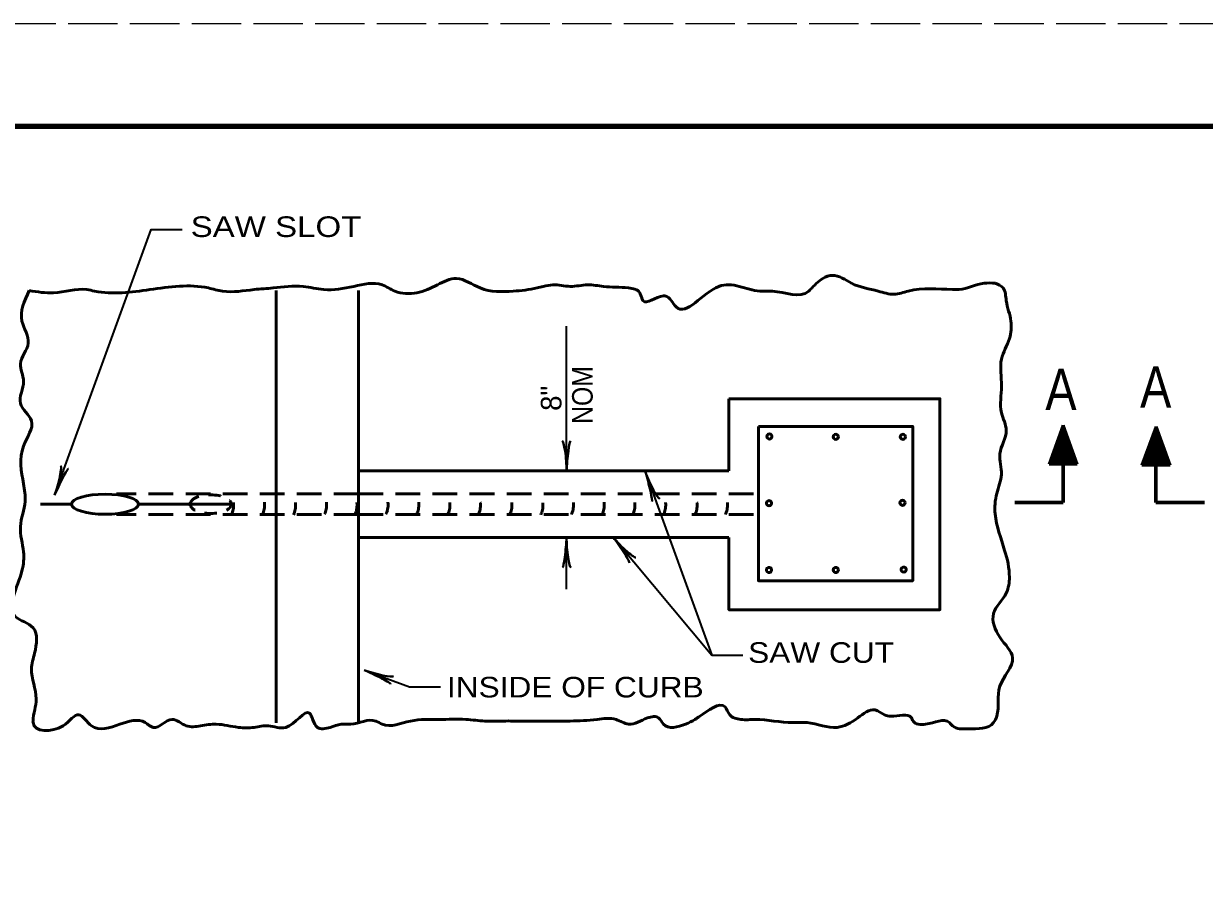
# Model space of a CAD drawing. Extents: x -58 to 622, y -372 to 68.
# Drawn here: x 3.2 to 118, y -15.7 to 68 of the extents above; entities that cross this region are included whole.
import ezdxf

# ---------------------------------------------------------------- set-up
doc = ezdxf.new("R2010")
doc.units = 0
doc.header["$LTSCALE"] = 0.8
for name, pattern in [('LONG_DASHED', [7.5, 6, -1.5]), ('MEDIUM_DASHED', [4.5, 3, -1.5]), ('SHORT_DASHED', [2.7, 1.5, -1.2])]:
    doc.linetypes.add(name, pattern=pattern)
doc.layers.add('1', color=7, linetype='Continuous', lineweight=35)
doc.layers.add('61', color=7, linetype='Continuous', lineweight=35)

msp = doc.modelspace()

# ---------------------------------------------------------------- linework, layer by layer
at = {"layer": '1', "lineweight": 53}
for p, q in [((27.7826, 42.0557), (27.7826, 0.0557)), ((35.7826, 42.0557), (35.7826, 0.0557)), ((71.7826, 24.5557), (71.7826, 31.5557)), ((104.2712, 28.9673), (102.9032, 25.2086)), ((104.2712, 28.9673), (105.6393, 25.2086)), ((113.2923, 28.8522), (111.9243, 25.0935)), ((113.2923, 28.8522), (114.6604, 25.0935)), ((35.7826, 24.5557), (71.7826, 24.5557)), ((102.9032, 25.2086), (105.6393, 25.2086)), ((111.9243, 25.0935), (114.6604, 25.0935)), ((7.8699, 21.3127), (4.8699, 21.3127)), ((14.3764, 21.2934), (23.4164, 21.2934)), ((35.7826, 18.0557), (71.7826, 18.0557))]:
    msp.add_line(p, q, dxfattribs=at)
at = {"layer": '1'}
for p, q in [((56.0009, 24.5898), (56.0009, 38.6044)), ((63.6731, 24.3975), (70.135, 6.6434)), ((56.0009, 13.0557), (56.0009, 18.039))]:
    msp.add_line(p, q, dxfattribs=at)
at = {"layer": '1', "lineweight": 60}
for p, q in [((104.2712, 21.4673), (104.2712, 28.9673)), ((113.2712, 21.4673), (113.2712, 28.4673)), ((99.5571, 21.4673), (104.2712, 21.4673)), ((113.2712, 21.4673), (117.9854, 21.4673))]:
    msp.add_line(p, q, dxfattribs=at)
at = {"layer": '1', "linetype": 'MEDIUM_DASHED', "lineweight": 53}
for p, q in [((35.7826, 22.3057), (12.2447, 22.3057)), ((35.7826, 22.3057), (74.6402, 22.3057)), ((35.7826, 20.3057), (12.2447, 20.3057)), ((35.7826, 20.3057), (74.6402, 20.3057))]:
    msp.add_line(p, q, dxfattribs=at)
at = {"layer": '1'}
for points in [[(6.2503, 22.1841), (15.6422, 47.9881), (18.6423, 47.9881)], [(60.5589, 18.0557), (70.135, 6.6434), (73.135, 6.6434)], [(36.3312, 5.1835), (40.7482, 3.5757), (43.7482, 3.5757)]]:
    msp.add_lwpolyline(points, dxfattribs=at)
at = {"layer": '1', "lineweight": 53}
for points in [[(71.7826, 18.0557), (71.7826, 11.0557), (92.2826, 11.0557), (92.2826, 31.5557), (71.7826, 31.5557)], [(104.893, 26.9856), (103.703, 27.0432), (104.8162, 27.1007), (103.703, 27.1583), (104.7394, 27.1775), (103.7606, 27.2351), (104.7011, 27.2542), (103.8566, 27.3311), (104.7011, 27.3694), (103.7797, 27.427), (104.6435, 27.4846), (103.8757, 27.523), (104.6627, 27.5422), (103.8566, 27.6382), (104.5475, 27.6382), (103.9333, 27.7342), (104.5859, 27.7342), (103.9909, 27.8109), (104.4899, 27.8877), (104.0101, 27.8877), (104.4707, 27.9644), (104.0868, 28.0412), (104.4707, 28.0988), (104.0101, 27.9644), (104.394, 28.1947), (104.0485, 28.1372), (104.4132, 28.3099), (104.0868, 28.2907), (104.3556, 28.3867), (104.202, 28.4443), (104.3364, 28.5211), (104.1828, 28.6363), (103.012, 25.3157), (104.2404, 28.5787), (103.0696, 25.3541), (104.2596, 28.4443), (103.2232, 25.4117), (103.9909, 27.7149), (103.0888, 25.4117), (104.3364, 28.617)], [(104.3364, 28.617), (105.5264, 25.2773), (104.3364, 28.4251), (105.4112, 25.4692), (104.4323, 27.9261), (105.2193, 25.738), (104.3172, 28.0412), (105.0657, 25.9108), (104.7011, 25.8532), (105.1809, 25.6612), (103.2807, 25.6037), (103.2999, 25.7188), (103.607, 25.738), (103.7414, 26.0067), (103.4727, 26.0451), (105.488, 25.3733), (105.0466, 25.9683), (103.7414, 26.0067), (103.5878, 26.1987), (103.0504, 25.3925), (103.8757, 27.2735)], [(113.9141, 26.8705), (112.7241, 26.9281), (113.8373, 26.9857), (112.7241, 27.0433), (113.7605, 27.0624), (112.7817, 27.12), (113.7222, 27.1392), (112.8777, 27.216), (113.7222, 27.2543), (112.8008, 27.3119), (113.6646, 27.3695), (112.8968, 27.4079), (113.6837, 27.4271), (112.8777, 27.5231), (113.5686, 27.5231), (112.9544, 27.6191), (113.607, 27.6191), (113.012, 27.6958), (113.511, 27.7726), (113.0312, 27.7726), (113.4918, 27.8493), (113.1079, 27.9262), (113.4918, 27.9838), (113.0312, 27.8493), (113.4151, 28.0797), (113.0696, 28.0221), (113.4342, 28.1948), (113.1079, 28.1757), (113.3767, 28.2717), (113.2231, 28.3292), (113.3575, 28.406), (113.2039, 28.5212), (112.0331, 25.2007), (113.2615, 28.4636), (112.0907, 25.239), (113.2807, 28.3292), (112.2442, 25.2966), (113.012, 27.5998), (112.1099, 25.2966), (113.3575, 28.5019)], [(113.3575, 28.5019), (114.5475, 25.1623), (113.3575, 28.31), (114.4323, 25.3542), (113.4534, 27.811), (114.2403, 25.6229), (113.3383, 27.9262), (114.0868, 25.7957), (113.7222, 25.7381), (114.202, 25.5462), (112.3018, 25.4886), (112.321, 25.6037), (112.6281, 25.6229), (112.7625, 25.8916), (112.4937, 25.93), (114.5091, 25.2583), (114.0677, 25.8532), (112.7625, 25.8916), (112.6089, 26.0836), (112.0715, 25.2774), (112.8968, 27.1584)], [(102.9928, 25.2773), (105.488, 25.2773), (105.4688, 25.3733), (103.0504, 25.3541), (105.392, 25.4309), (103.0504, 25.4501), (105.3537, 25.5077), (103.1272, 25.5652), (105.3152, 25.6228), (103.2232, 25.5268), (105.4112, 25.5268), (105.2768, 25.738), (103.1656, 25.6804), (105.2577, 25.8148), (103.2615, 25.8148), (105.1425, 25.9491), (103.2999, 25.9299), (105.2193, 26.0259), (103.3767, 26.0642), (105.1617, 26.1411), (103.3767, 26.1794), (105.1425, 26.2178), (103.3959, 26.2754), (105.0657, 26.3138), (103.3959, 26.3522), (105.0466, 26.3714), (103.5302, 26.4097), (105.0273, 26.4673), (103.4727, 26.4673), (104.9506, 26.5825), (103.4918, 26.5442), (104.9314, 26.6593), (103.4918, 26.6209), (104.9506, 26.7361), (103.5302, 26.7168), (104.9506, 26.832), (103.5687, 26.8128), (104.893, 26.9088), (103.607, 26.928), (104.893, 26.9856)], [(112.0139, 25.1623), (114.5091, 25.1623), (114.4899, 25.2583), (112.0715, 25.239), (114.4131, 25.3158), (112.0715, 25.335), (114.3747, 25.3926), (112.1482, 25.4502), (114.3363, 25.5077), (112.2442, 25.4117), (114.4323, 25.4117), (114.2979, 25.6229), (112.1867, 25.5653), (114.2788, 25.6997), (112.2826, 25.6997), (114.1636, 25.834), (112.321, 25.8148), (114.2403, 25.9108), (112.3978, 25.9492), (114.1827, 26.026), (112.3978, 26.0643), (114.1636, 26.1028), (112.417, 26.1603), (114.0868, 26.1988), (112.417, 26.2371), (114.0677, 26.2563), (112.5513, 26.2947), (114.0484, 26.3522), (112.4937, 26.3522), (113.9717, 26.4674), (112.5129, 26.4291), (113.9525, 26.5442), (112.5129, 26.5058), (113.9717, 26.621), (112.5513, 26.6017), (113.9717, 26.7169), (112.5897, 26.6977), (113.9141, 26.7937), (112.6281, 26.8129), (113.9141, 26.8705)]]:
    msp.add_lwpolyline(points, dxfattribs=at)
msp.add_lwpolyline([(74.6402, 28.8667), (74.6402, 13.8667), (89.6402, 13.8667), (89.6402, 28.8667)], close=True, dxfattribs=at)
for centre in [(75.7151, 27.8881), (82.1636, 27.8497), (88.6889, 27.8497), (75.6767, 21.4012), (88.6505, 21.4395), (75.6767, 14.9142), (82.1636, 14.9142), (88.7657, 14.9526)]:
    msp.add_circle(centre, 0.25, dxfattribs=at)
at = {"layer": '1', "linetype": 'SHORT_DASHED', "lineweight": 53}
for centre in [(21.4742, 21.2253), (24.4874, 21.2445), (27.5005, 21.2061), (30.5138, 21.2445), (33.4694, 21.2253), (36.4826, 21.2445), (39.4766, 21.2445), (42.4898, 21.2061), (45.4645, 21.2254), (48.5161, 21.2061), (51.5293, 21.187), (54.5041, 21.2254), (57.4981, 21.2445), (60.4729, 21.2254), (63.4669, 21.2062), (66.5185, 21.2062), (69.4743, 21.2254)]:
    msp.add_arc(centre, 2.1707, 334.94384, 29.7373, dxfattribs=at)
at = {"layer": '1', "lineweight": 40}
for centre, major_axis, ratio, start_param, end_param in [((55.7246, 25.681), (0.1562, -1.7857), 0.122415, 0.89635335, 3.14159265), ((56.2125, 25.7103), (0.1757, 1.7565), 0.07063, 6.28230741, 8.55970261), ((6.3639, 23.304), (-0.464, -1.7314), 0.122415, 0.89635335, 3.14159265), ((6.8324, 23.1646), (0.7658, 1.5904), 0.07063, 6.28230741, 8.55970261), ((63.8575, 23.2722), (-0.4357, 1.7106), 0.07063, 3.14071475, 5.41810995), ((64.3059, 23.4666), (-0.7575, 1.6246), 0.122415, 0.89635335, 3.14159265), ((55.7893, 16.9185), (-0.1757, -1.7565), 0.07063, 6.28230741, 8.55970261), ((56.2772, 16.9478), (-0.1562, 1.7857), 0.122415, 0.89635335, 3.14159265), ((61.1171, 17.0613), (0.9945, -1.4584), 0.07063, 6.28230741, 8.55970261), ((61.1171, 17.0613), (0.9945, -1.4584), 0.07063, 6.28230741, 8.55970261), ((61.472, 17.3974), (-1.2674, 1.2675), 0.122415, 0.89635335, 3.14159265), ((61.472, 17.3974), (-1.2674, 1.2675), 0.122415, 0.89635335, 3.14159265), ((37.3118, 4.6014), (1.5904, -0.7658), 0.07063, 6.28230741, 8.55970261), ((37.4511, 5.0699), (-1.7314, 0.464), 0.122415, 0.89635335, 3.14159265)]:
    msp.add_ellipse(centre, major_axis=major_axis, ratio=ratio, start_param=start_param, end_param=end_param, dxfattribs=at)
at = {"layer": '1', "lineweight": 53}
msp.add_ellipse((11.1456, 21.3057), major_axis=(-3.25, 0), ratio=0.300371, dxfattribs=at)
at = {"layer": '1', "linetype": 'SHORT_DASHED', "lineweight": 53}
msp.add_ellipse((21.4166, 21.3057), major_axis=(-2, 0), ratio=0.452986, dxfattribs=at)
at = {"layer": '1', "lineweight": 53}
for points in [[(97.6571, 42.7712), (98.4248, 42.3105), (98.7319, 41.0822), (99.1925, 39.086), (99.039, 37.397), (98.2712, 35.4008), (98.2712, 32.7906), (98.2712, 30.1802), (98.7319, 28.4912), (98.1177, 26.188), (98.2712, 24.1918), (97.8106, 22.3492), (97.6571, 20.3532), (98.5783, 16.8216), (99.039, 14.2112), (98.7319, 12.6757), (97.5035, 10.6797), (98.1177, 8.3764), (99.3461, 6.3803), (98.1177, 3.6164), (97.8106, 0.699), (97.5035, 0.0848), (95.0468, -0.5293), (93.5113, -0.2223), (93.2042, 0.0848), (90.9009, -0.0687), (89.6726, 0.2384), (89.519, 0.5455), (87.5229, 0.699), (86.9087, 0.8526), (85.9874, 1.3133), (84.2983, 0.5455), (82.3023, -0.3758), (79.3848, 0.0848), (78.0029, 0.0848), (74.3178, 0.3919), (72.9358, 0.3919), (71.861, 0.8526), (71.4003, 1.6203), (68.9436, 0.699), (68.4829, 0.3919), (67.5617, -0.0687), (65.412, -0.0687), (64.9513, 0.5455), (63.8765, 0.5455), (62.0339, -0.0687), (60.8055, 0.3919), (58.9629, 0.3919), (56.3527, 0.2384), (54.6636, 0.2384), (51.5927, 0.2384), (49.5965, 0.2384), (48.0611, 0.2384), (46.2185, 0.3919), (43.6082, 0.3919), (40.8443, 0.2384), (38.0804, -0.0687), (37.4663, 0.2384), (35.0095, -0.0687), (34.0882, -0.0687), (33.0133, -0.3758), (31.785, -0.3758), (31.0173, 1.0061), (28.714, -0.3758), (27.025, -0.2223), (25.6431, -0.3758), (24.1076, -0.3758), (21.9579, -0.0687), (20.4224, -0.2223), (19.0405, -0.2223), (17.6586, 0.3919), (15.816, -0.3758), (15.0482, 0.0848), (12.5915, -0.0687), (9.8276, -0.2223), (8.5992, 0.8526), (7.0637, -0.2223), (4.1463, 0.0848), (4.1463, 0.2384), (4.4534, 2.3881), (3.9928, 5.3054), (4.2999, 6.8409), (4.1463, 9.2977), (2.4573, 10.3725), (3.0715, 14.8254), (3.2251, 16.668), (2.9179, 19.1247), (3.3786, 21.5816), (3.2251, 23.2706), (3.2251, 26.9557), (3.9928, 29.4125), (2.9179, 31.1015), (3.2251, 33.2512), (2.9179, 34.9402), (3.6857, 36.9363), (3.0715, 39.086), (3.7826, 42.0557)], [(3.7826, 42.0557), (6.1424, 41.8498), (9.367, 42.157), (10.1347, 42.0034), (15.5089, 42.157), (21.1902, 42.3105), (22.5721, 42.0034), (25.6431, 42.157), (27.4856, 42.3105), (30.403, 42.4641), (32.3992, 42.157), (35.3166, 42.4641), (38.0804, 42.6176), (39.3088, 42.0034), (41.4585, 41.8498), (43.4546, 42.6176), (45.2972, 43.2318), (47.6004, 42.3105), (50.8249, 42.0034), (53.1282, 42.3105), (53.7423, 42.4641), (54.6636, 42.6176), (56.3527, 42.4641), (58.0417, 42.6176), (59.5772, 42.4641), (62.0339, 42.3105), (63.1088, 41.8498), (63.4158, 41.0822), (65.412, 41.5427), (65.5655, 41.5427), (66.6403, 40.4679), (70.7862, 42.4641), (72.7822, 42.4641), (74.7784, 42.0034), (76.0067, 42.0034), (79.5384, 42.0034), (79.6919, 42.157), (80.9203, 43.2318), (81.8416, 43.5389), (83.6842, 42.7712), (86.2945, 42.0034), (87.83, 41.6963), (89.2119, 42.0034), (93.5113, 42.157), (94.1254, 42.157), (96.5822, 42.7712), (97.6571, 42.7712)]]:
    msp.add_spline(points, degree=3, dxfattribs=at)
at = {"layer": '61', "linetype": 'LONG_DASHED', "lineweight": 13}
msp.add_line((-58.4297, 67.9933), (621.5902, 67.9933), dxfattribs=at)
at = {"layer": '61', "lineweight": 158}
msp.add_lwpolyline([(610.6102, 57.9933), (-28.4297, 57.9933), (-28.4297, -362.0267)], dxfattribs=at)

# ---------------------------------------------------------------- texts
at = {"layer": '1'}
for s, height, width, p in [('SAW SLOT', 2, 1.2, (19.47, 47.2657)), ('A', 4, 0.85, (102.5354, 30.4629)), ('A', 4, 0.85, (111.742, 30.6989)), ('SAW CUT', 2, 1.15, (73.6469, 5.8954)), ('INSIDE OF CURB', 2, 1.15, (44.3749, 2.5315))]:
    msp.add_text(s, height=height, dxfattribs=dict(at, width=width)).set_placement(p)
at = {"layer": '1', "width": 0.9}
msp.add_text('NOM', height=2, rotation=90, dxfattribs=at).set_placement((58.5386, 29.1047))
at = {"layer": '1'}
msp.add_text('8"', height=2, rotation=90, dxfattribs=at).set_placement((55.4992, 30.3735))

doc.saveas('drawing.dxf')
